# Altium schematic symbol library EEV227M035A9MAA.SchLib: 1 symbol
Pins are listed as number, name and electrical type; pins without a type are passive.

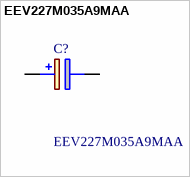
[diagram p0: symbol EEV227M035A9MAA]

## EEV227M035A9MAA
designator C?
EEV, Aluminum, Aluminum Electrolytic, 220 uF, 20%, 35 VDC, -55/+105C, 105C, -55C, 105C, 2,000 Hrs, 12 % , 160 mOhms, 0.42, 77 uA, 2, 3, 8mm, 10.2mm, 500; Manufacturer_Name: KEMET; Geometry.Height: 10.5mm
footprint CAPAE830X1050N
pins: 1 +, 2 -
